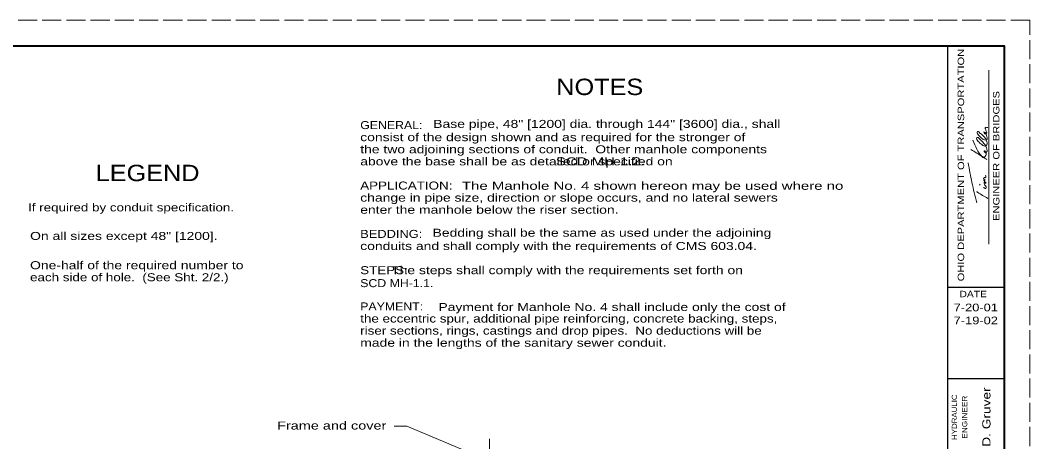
# Model space of a CAD drawing. Extents: x 1170.6 to 1204.6, y 975 to 1019.
# Drawn here: x 1184.91 to 1204.59, y 1010.8 to 1019.03 of the extents above; entities that cross this region are included whole.
import ezdxf
from ezdxf.enums import TextEntityAlignment as Align

# ---------------------------------------------------------------- set-up
doc = ezdxf.new("R2010")
doc.units = 0
doc.header["$LTSCALE"] = 0.062
doc.linetypes.add('DOT_DASHED', pattern=[7.7, 5, -1.2, 0.3, -1.2])
doc.linetypes.add('LONG_DASHED', pattern=[7.5, 6, -1.5])
doc.layers.add('1', color=7, linetype='Continuous', lineweight=13)

msp = doc.modelspace()

# ---------------------------------------------------------------- linework, layer by layer
at = {"layer": '1', "lineweight": 25}
for p, q in [((1172.59275, 1018.52625), (1204.09275, 1018.52625)), ((1202.99275, 997.52625), (1202.99275, 1018.52625)), ((1204.09275, 1018.52625), (1204.09275, 997.52625)), ((1204.09275, 1013.81042), (1202.99275, 1013.81042)), ((1204.09275, 1012.02625), (1202.99275, 1012.02625))]:
    msp.add_line(p, q, dxfattribs=at)
at = {"layer": '1'}
for p, q in [((1203.7915, 1014.65725), (1203.7915, 1018.04733)), ((1203.624, 1015.80817), (1203.61383, 1015.82742)), ((1192.44667, 1011.10092), (1192.19842, 1011.10092)), ((1193.51125, 1010.6515), (1192.44667, 1011.10092))]:
    msp.add_line(p, q, dxfattribs=at)
at = {"layer": '1', "linetype": 'DOT_DASHED'}
msp.add_line((1194.05933, 1009.93642), (1194.05933, 1010.90875), dxfattribs=at)
at = {"layer": '1', "linetype": 'LONG_DASHED'}
msp.add_lwpolyline([(1170.59275, 997.02625), (1204.59275, 997.02625), (1204.59275, 1019.02625), (1170.59275, 1019.02625)], close=True, dxfattribs=at)
at = {"layer": '1', "lineweight": 40}
msp.add_lwpolyline([(1172.59275, 1018.52625), (1204.09275, 1018.52625), (1204.09275, 997.52625), (1172.59275, 997.52625)], close=True, dxfattribs=at)
at = {"layer": '1'}
for points in [[(1203.48458, 1016.68325), (1203.66775, 1016.35492), (1203.68292, 1016.34433), (1203.69308, 1016.34433), (1203.725, 1016.368), (1203.74008, 1016.40217), (1203.73508, 1016.45342), (1203.71817, 1016.47525), (1203.70467, 1016.47525), (1203.70292, 1016.46225), (1203.71308, 1016.44708), (1203.72658, 1016.43867), (1203.74167, 1016.43867), (1203.75683, 1016.46025), (1203.76025, 1016.47958), (1203.75, 1016.53492), (1203.66775, 1016.65533), (1203.62225, 1016.7), (1203.58533, 1016.73458), (1203.56017, 1016.73675), (1203.56192, 1016.69817), (1203.58708, 1016.65942), (1203.65433, 1016.59708), (1203.69642, 1016.57167), (1203.73008, 1016.56717), (1203.75342, 1016.59317), (1203.76025, 1016.62733), (1203.75517, 1016.65308), (1203.725, 1016.72625), (1203.69475, 1016.75825), (1203.63417, 1016.81167), (1203.6055, 1016.8375), (1203.572, 1016.85275), (1203.56858, 1016.82475), (1203.57867, 1016.79892), (1203.63583, 1016.739), (1203.7065, 1016.69175), (1203.7585, 1016.69408), (1203.75683, 1016.75175), (1203.745, 1016.79467), (1203.73167, 1016.82042), (1203.7215, 1016.83117), (1203.69808, 1016.84617), (1203.69983, 1016.82908), (1203.73508, 1016.80758), (1203.75, 1016.81833), (1203.73692, 1016.872), (1203.72833, 1016.89992), (1203.725, 1016.91258), (1203.725, 1016.92542), (1203.725, 1016.93408), (1203.75, 1016.93192), (1203.77542, 1016.93192)], [(1203.44575, 1016.501), (1203.6695, 1016.3635), (1203.75517, 1016.30783)], [(1203.562, 1015.464), (1203.46333, 1015.85925), (1203.39208, 1016.24158)], [(1203.69308, 1015.76292), (1203.70133, 1015.75225), (1203.7385, 1015.73933), (1203.74325, 1015.77175), (1203.71817, 1015.80817), (1203.70292, 1015.84442), (1203.70292, 1015.86367), (1203.71817, 1015.85742), (1203.72833, 1015.84658), (1203.7385, 1015.84225), (1203.71483, 1015.87442), (1203.70292, 1015.88942), (1203.69983, 1015.90675), (1203.72325, 1015.90017), (1203.71483, 1015.90883), (1203.68967, 1015.93667), (1203.69983, 1015.95183), (1203.71658, 1015.95383), (1203.725, 1015.95183), (1203.73508, 1015.97317), (1203.72833, 1016.00108)], [(1203.77717, 1015.54842), (1203.572, 1015.66842), (1203.55642, 1015.67883)]]:
    msp.add_spline(points, degree=3, dxfattribs=at)

# ---------------------------------------------------------------- texts
for s, height, width, p in [('OHIO DEPARTMENT OF TRANSPORTATION', 0.125, 1.3, (1203.31267, 1016.1985)), ('ENGINEER OF BRIDGES', 0.125, 1.3, (1204.001, 1016.37529)), ('D. Gruver', 0.16, 1.25, (1203.82617, 1011.28042)), ('HYDRAULIC', 0.1, 1.15, (1203.17183, 1011.27733)), ('ENGINEER', 0.1, 1.2, (1203.37275, 1011.27738))]:
    msp.add_text(s, height=height, rotation=90, dxfattribs=dict(at, width=width)).set_placement(p, align=Align.CENTER)
for s, height, width, p in [('NOTES', 0.32, 1.15, (1195.36208, 1017.56408)), ('GENERAL:', 0.156, 1.15, (1191.53967, 1016.90042)), ('Base pipe, 48" [1200] dia. through 144" [3600] dia., shall', 0.156, 1.3, (1192.96308, 1016.92358)), ('consist of the design shown and as required for the stronger of', 0.156, 1.3, (1191.53967, 1016.66442)), ('the two adjoining sections of conduit.  Other manhole components', 0.156, 1.3, (1191.53967, 1016.42842)), ('LEGEND', 0.32, 1.15, (1186.383, 1015.88417)), ('above the base shall be as detailed or specified on', 0.156, 1.3, (1191.53967, 1016.19242)), ('                                               SCD MH-1.2.', 0.156, 1.4, (1191.53967, 1016.19242)), ('APPLICATION:', 0.156, 1.25, (1191.53967, 1015.72042)), ('The Manhole No. 4 shown hereon may be used where no ', 0.156, 1.4, (1193.522, 1015.71517)), ('change in pipe size, direction or slope occurs, and no lateral sewers ', 0.156, 1.3, (1191.53967, 1015.48442)), ('If required by conduit specification.', 0.156, 1.25, (1185.06483, 1015.29375)), ('enter the manhole below the riser section.  ', 0.156, 1.3, (1191.53967, 1015.24842)), ('On all sizes except 48" [1200].', 0.156, 1.3, (1185.10417, 1014.73683)), ('BEDDING:', 0.156, 1.2, (1191.53967, 1014.77642)), ('Bedding shall be the same as used under the adjoining', 0.156, 1.3, (1192.95017, 1014.7995)), ('conduits and shall comply with the requirements of CMS 603.04.', 0.156, 1.3, (1191.53967, 1014.54042)), ('One-half of the required number to', 0.156, 1.3, (1185.10325, 1014.16533)), ('STEPS:', 0.156, 1.25, (1191.53967, 1014.06842)), ('        The steps shall comply with the requirements set forth on', 0.156, 1.3, (1191.53967, 1014.06842)), ('each side of hole.  (See Sht. 2/2.)', 0.156, 1.25, (1185.10325, 1013.93067)), ('SCD MH-1.1.', 0.156, 1.15, (1191.53967, 1013.81567)), ('PAYMENT:', 0.156, 1.15, (1191.53967, 1013.36042)), ('Payment for Manhole No. 4 shall include only the cost of ', 0.156, 1.3, (1193.06375, 1013.3495)), ('the eccentric spur, additional pipe reinforcing, concrete backing, steps,', 0.156, 1.25, (1191.53967, 1013.12442)), ('riser sections, rings, castings and drop pipes.  No deductions will be', 0.156, 1.25, (1191.53967, 1012.88842)), ('made in the lengths of the sanitary sewer conduit.', 0.156, 1.3, (1191.53967, 1012.65242)), ('Frame and cover', 0.156, 1.35, (1189.91958, 1011.03575))]:
    msp.add_text(s, height=height, dxfattribs=dict(at, width=width)).set_placement(p)
for s, height, width, p in [('DATE', 0.125, 1.2, (1203.48946, 1013.619)), ('7-20-01', 0.15, 1.25, (1203.53979, 1013.3435)), ('7-19-02', 0.15, 1.25, (1203.53979, 1013.09042))]:
    msp.add_text(s, height=height, dxfattribs=dict(at, width=width)).set_placement(p, align=Align.CENTER)

doc.saveas('drawing.dxf')
